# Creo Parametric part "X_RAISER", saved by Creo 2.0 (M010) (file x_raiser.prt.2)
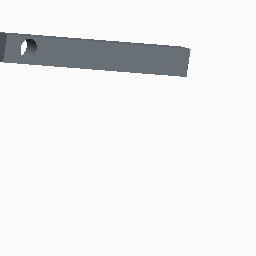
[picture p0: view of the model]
Units: Inch lbm Second (Pro/E Default); INCH, POUND, SECS

Created from: INLBS_PART_SOLID.PRT

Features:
  1. datum plane "RIGHT"
  2. datum plane "TOP"
  3. datum plane "FRONT"
  4. coordinate system
  5. sketch "Sketch 1"
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
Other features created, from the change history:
  extrusion "Extrude 1"
  sketch "Sketch 2"
  extruded cut "Extrude 2"

Surfaces: 9 plane, 2 cylinder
